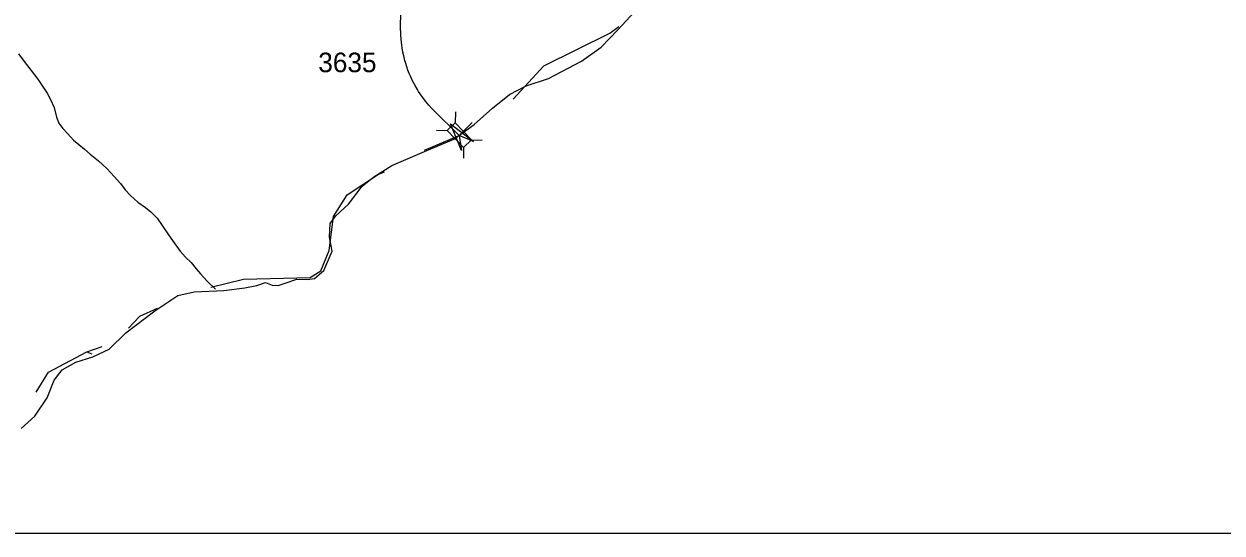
# Model space of a CAD drawing. Extents: x 1383679 to 1536984, y 460658 to 651027.
# Drawn here: x 1449882 to 1457529, y 461213 to 464459 of the extents above; entities that cross this region are included whole.
import ezdxf

# ---------------------------------------------------------------- set-up
doc = ezdxf.new("R2010")
doc.units = 0
for name, color, linetype in [('Exist Boundary Political CountyLine', 7, 'Continuous'), ('Exist Hydrographic Creek Single Shore', 7, 'Continuous'), ('Exist Hydrographic Misc Water Feature', 7, 'Continuous'), ('Exist Road Secondary Structure Standard Bridge Attributed CELL', 7, 'Continuous'), ('Exist Road Secondary Structure Standard Bridge CELL', 7, 'Continuous'), ('Exist Road Secondary Type 51 Attributed', 7, 'Continuous'), ('Exist Road Secondary Type 51 Number Label', 7, 'Continuous'), ('Map Preparation Inset Cut Line', 7, 'Continuous')]:
    doc.layers.add(name, color=color, linetype=linetype)

msp = doc.modelspace()

# ---------------------------------------------------------------- linework, layer by layer
at = {"layer": 'Exist Boundary Political CountyLine'}
msp.add_lwpolyline([(1449865, 461879.6), (1449950.6, 461957.9), (1450030.8, 462074.6), (1450074.9, 462187.9), (1450126.1, 462254.9), (1450213.1, 462303.4), (1450321.6, 462337.4), (1450426.6, 462385.5), (1450532.6, 462489.7), (1450717.1, 462630.2), (1450864.9, 462727.7), (1450969.4, 462751.8), (1451157.7, 462760.4), (1451292.1, 462775.9), (1451368.4, 462792.4), (1451424.7, 462811.5), (1451466.5, 462794.6), (1451504.5, 462792), (1451548.8, 462807.2), (1451623.2, 462831.9), (1451691.2, 462830.7), (1451737.3, 462835.8), (1451796.3, 462886.8), (1451848.6, 463009.8), (1451832.3, 463100.2), (1451835.8, 463186.2), (1451872.6, 463235.4), (1451954.1, 463310), (1452040.3, 463424.5), (1452115.3, 463485.1), (1452230.6, 463557), (1452438.5, 463645.2), (1452626, 463723.9), (1452755.7, 463817.5), (1452873.7, 463923.4), (1452981.3, 464009.5), (1453088.3, 464065.5), (1453229.2, 464111.1), (1453441.4, 464221.3), (1453567, 464311), (1453673.1, 464421.1), (1453805.9, 464566.7)], dxfattribs=at)
at = {"layer": 'Exist Hydrographic Creek Single Shore'}
for points in [[(1453005.3, 463980.4), (1453201.1, 464191.7), (1453622.1, 464399.9), (1453679.2, 464443.1)], [(1452438.2, 463655.2), (1452661, 463749.1), (1452742, 463831.8)], [(1451075.1, 462780.8), (1451284.1, 462832), (1451709.1, 462843.1), (1451776.1, 462884.4), (1451829.1, 463014.7), (1451858.1, 463230.7), (1451944.1, 463370.1), (1452146.1, 463500.6), (1452182.6, 463517.3)], [(1450549.5, 462519), (1450621.1, 462595.8), (1450735.3, 462647.7)], [(1449960.7, 462111.1), (1450039.1, 462239.9), (1450283.1, 462369.6)], [(1450283.1, 462369.6), (1450381.3, 462402.5)], [(1450283.1, 462369.6), (1450315, 462356.5)]]:
    msp.add_lwpolyline(points, dxfattribs=at)
at = {"layer": 'Exist Hydrographic Misc Water Feature'}
for points in [[(1449846.4, 464268), (1449883.5, 464219.7), (1449928.5, 464163), (1449971.5, 464107.9), (1450029.9, 464019), (1450051.1, 463978.3), (1450074.2, 463926.1), (1450089.1, 463865.1), (1450104.4, 463827.1), (1450129.8, 463792.9), (1450161.2, 463757.8)], [(1450161.2, 463757.8), (1450198.5, 463717.7), (1450232, 463690.7), (1450267.5, 463660.5), (1450304.9, 463629.4), (1450358.2, 463586.5), (1450411.3, 463537.8), (1450458.4, 463486.8), (1450497.5, 463441.7), (1450528.8, 463401.7), (1450562.3, 463366.5), (1450609.4, 463322.1), (1450656.9, 463289.1), (1450692.3, 463260.5), (1450731.7, 463221.2), (1450764.8, 463174.5), (1450803.7, 463113.8), (1450831, 463078), (1450879.8, 463010.6), (1450913.2, 462972.1), (1450948.5, 462937.8), (1450981.9, 462896.9), (1451009.3, 462866), (1451052.5, 462819.2), (1451103.6, 462768.9)]]:
    msp.add_lwpolyline(points, dxfattribs=at)
at = {"layer": 'Exist Road Secondary Structure Standard Bridge Attributed CELL'}
msp.add_lwpolyline([(1452675.7, 463652.8), (1452605, 463821.5), (1452750.5, 463710.7), (1452661, 463749.1)], close=True, dxfattribs=at)
at = {"layer": 'Exist Road Secondary Structure Standard Bridge CELL'}
for p, q in [((1452636.3, 463898.4), (1452634.5, 463829.4)), ((1452514.4, 463782.5), (1452583.3, 463780.8)), ((1452688.3, 463672.1), (1452686.6, 463603.1)), ((1452738.3, 463719.6), (1452807.3, 463717.8))]:
    msp.add_line(p, q, dxfattribs=at)
msp.add_lwpolyline([(1452634.5, 463829.4), (1452738.6, 463719.8), (1452687.4, 463671.2), (1452583.3, 463780.8)], close=True, dxfattribs=at)
at = {"layer": 'Exist Road Secondary Type 51 Attributed'}
msp.add_lwpolyline([(1452661, 463749.1), (1452604.9, 463802.7), (1452551.9, 463854.8), (1452519.8, 463887.1), (1452486, 463920.5), (1452465.6, 463942.3), (1452444.8, 463966.8), (1452427, 463990.1), (1452410.2, 464014.1), (1452401.2, 464028.7), (1452393.6, 464041.6), (1452378.8, 464067.2), (1452363, 464096.8), (1452349.2, 464126.3), (1452341.2, 464144.4), (1452333.2, 464165), (1452318.8, 464207.9), (1452313.5, 464225.3), (1452311.4, 464233.8), (1452306.1, 464255.4), (1452300.2, 464279.5), (1452295.7, 464307.2), (1452291.7, 464342.1), (1452288.6, 464387.5), (1452286.4, 464445.4), (1452287, 464524.9)], dxfattribs=at)
at = {"layer": 'Map Preparation Inset Cut Line'}
msp.add_lwpolyline([(1437474.3, 477316), (1437474.3, 461213.3), (1475802.8, 461213.3), (1475802.8, 477316), (1437474.3, 477316)], dxfattribs=at)

# ---------------------------------------------------------------- texts
at = {"layer": 'Exist Road Secondary Type 51 Number Label'}
msp.add_text('3635', height=125, dxfattribs=at).set_placement((1451760.6, 464151.6))

doc.saveas('drawing.dxf')
